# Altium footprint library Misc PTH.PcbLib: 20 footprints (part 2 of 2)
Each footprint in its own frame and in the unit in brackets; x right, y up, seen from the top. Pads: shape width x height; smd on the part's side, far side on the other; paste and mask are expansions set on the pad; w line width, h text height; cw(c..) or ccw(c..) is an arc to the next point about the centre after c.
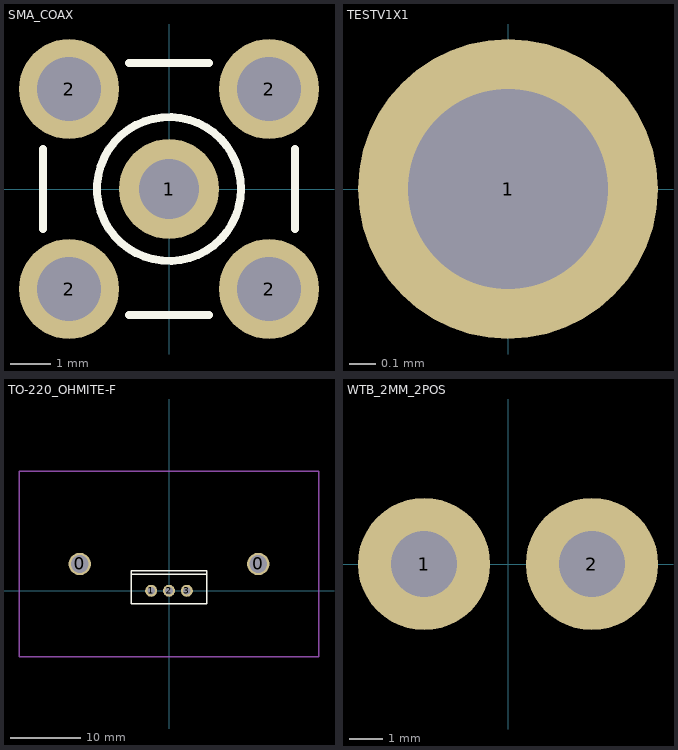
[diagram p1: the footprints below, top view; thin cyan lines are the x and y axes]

## SMA_COAX [mm] "Connector; SMA Straight"
height 9.5
pads (5):
  round 2.5 hole 1.5: 1(0,0)
  round 2.5 hole 1.6: 2(-2.5,-2.5) 2(-2.5,2.5) 2(2.5,-2.5) 2(2.5,2.5)
Top Overlay:
  circle w0.2: c0,0 r1.8
  lines w0.2: -3.15,-1 -3.15,1 ; -1,-3.15 1,-3.15 ; -1,3.15 1,3.15 ; 3.15,-1 3.15,1
Mechanical 1:
  circle w0.025: c0,0 r0.2
  circle w0.025: c0,0 r1.05
  circle w0.025: c0,0 r1.8

## TESTV1X1 [mil]
pads (1):
  round 45 hole 30 paste-200: 1(0,0)
Mechanical 15:
  lines w5: -10,0 10,0 ; 0,-10 0,10

## TO-220_OHMITE-F [mm] "TO, Thru-Hole, Vertical, Heatsink Mounted; 3 In-Line Leads; Pitch 2.54 mm"
height 0.635
pads (5):
  round 3.175 hole 2.54: 0(-12.7,3.81) 0(12.7,3.81)
  round 1.7 hole 1.1: 1(-2.54,0) 2(0,0) 3(2.54,0)
Top Overlay:
  lines w0.2: -5.35,2.35 5.35,2.35 ; -5.35,-1.85 5.35,-1.85 5.35,2.85 -5.35,2.85 -5.35,-1.85
Mechanical 15:
  lines w0.2: -21.336,-9.398 21.336,-9.398 21.336,17.018 -21.336,17.018 -21.336,-9.398
3D body: height 63.5, standoff 0, extent -20.828,-8.89 20.828,16.51

## WTB_2MM_2POS [mm] "Wire-to-board, 2mm hole, 2 positions"
pads (2):
  round 4 hole 2 mask+0: 1(-2.54,0) 2(2.54,0)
